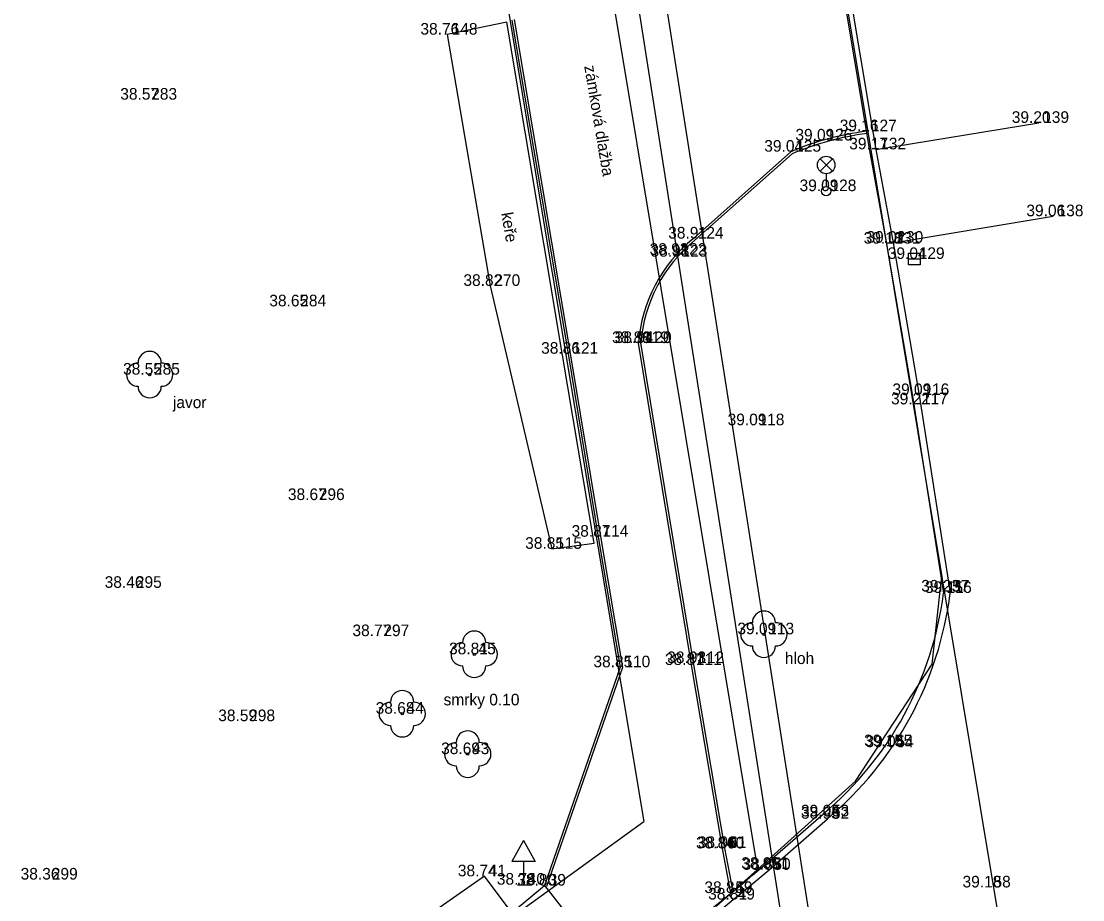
# Model space of a CAD drawing. Extents: x -609709 to -609357, y -1051535 to -1051131.
# Drawn here: x -609522.37 to -609499.5, y -1051316.16 to -1051297.25 of the extents above; entities that cross this region are included whole.
import ezdxf

# ---------------------------------------------------------------- set-up
doc = ezdxf.new("R2010")
doc.units = 0
for name, color, linetype in [('Vrstva 1', 7, 'Continuous'), ('Vrstva 10', 7, 'Continuous'), ('Vrstva 19', 7, 'Continuous'), ('Vrstva 2', 7, 'Continuous'), ('Vrstva 3', 7, 'Continuous'), ('Vrstva 4', 7, 'Continuous'), ('Vrstva 5', 7, 'Continuous'), ('Vrstva 7', 7, 'Continuous')]:
    doc.layers.add(name, color=color, linetype=linetype)

msp = doc.modelspace()

# ---------------------------------------------------------------- linework, layer by layer
at = {"layer": 'Vrstva 1'}
for p, q in [((-609513.19, -1051297.54), (-609513.19, -1051297.54)), ((-609519.66, -1051298.94), (-609519.66, -1051298.94)), ((-609500.45, -1051299.44), (-609500.45, -1051299.44)), ((-609504.16, -1051299.62), (-609504.16, -1051299.62)), ((-609505.12, -1051299.82), (-609505.12, -1051299.82)), ((-609505.79, -1051300.06), (-609505.79, -1051300.06)), ((-609503.96, -1051300.01), (-609503.96, -1051300.01)), ((-609505.03, -1051300.91), (-609505.03, -1051300.91)), ((-609500.14, -1051301.45), (-609500.14, -1051301.45)), ((-609507.89, -1051301.93), (-609507.89, -1051301.93)), ((-609503.65, -1051302.04), (-609503.65, -1051302.04)), ((-609503.59, -1051302.02), (-609503.59, -1051302.02)), ((-609508.26, -1051302.28), (-609508.26, -1051302.28)), ((-609508.24, -1051302.32), (-609508.24, -1051302.32)), ((-609503.13, -1051302.37), (-609503.13, -1051302.37)), ((-609512.27, -1051302.95), (-609512.27, -1051302.95)), ((-609516.45, -1051303.39), (-609516.45, -1051303.39)), ((-609509.07, -1051304.18), (-609509.07, -1051304.18)), ((-609509.01, -1051304.18), (-609509.01, -1051304.18)), ((-609510.59, -1051304.41), (-609510.59, -1051304.41)), ((-609519.6, -1051304.86), (-609519.6, -1051304.86)), ((-609503.03, -1051305.3), (-609503.03, -1051305.3)), ((-609503.06, -1051305.5), (-609503.06, -1051305.5)), ((-609506.58, -1051305.95), (-609506.58, -1051305.95)), ((-609516.05, -1051307.56), (-609516.05, -1051307.56)), ((-609509.94, -1051308.35), (-609509.94, -1051308.35)), ((-609510.94, -1051308.61), (-609510.94, -1051308.61)), ((-609519.99, -1051309.45), (-609519.99, -1051309.45)), ((-609502.41, -1051309.53), (-609502.41, -1051309.53)), ((-609502.36, -1051309.56), (-609502.36, -1051309.56)), ((-609514.66, -1051310.49), (-609514.66, -1051310.49)), ((-609506.37, -1051310.45), (-609506.37, -1051310.45)), ((-609512.61, -1051310.88), (-609512.61, -1051310.88)), ((-609509.47, -1051311.16), (-609509.47, -1051311.16)), ((-609507.93, -1051311.11), (-609507.93, -1051311.11)), ((-609507.88, -1051311.07), (-609507.88, -1051311.07)), ((-609517.55, -1051312.32), (-609517.55, -1051312.32)), ((-609514.16, -1051312.16), (-609514.16, -1051312.16)), ((-609512.75, -1051313.03), (-609512.75, -1051313.03)), ((-609503.64, -1051312.86), (-609503.64, -1051312.86)), ((-609503.61, -1051312.88), (-609503.61, -1051312.88)), ((-609505, -1051314.37), (-609505, -1051314.37)), ((-609505, -1051314.42), (-609505, -1051314.42)), ((-609507.26, -1051315.06), (-609507.26, -1051315.06)), ((-609507.21, -1051315.05), (-609507.21, -1051315.05)), ((-609506.28, -1051315.5), (-609506.28, -1051315.5)), ((-609506.26, -1051315.52), (-609506.26, -1051315.52)), ((-609521.8, -1051315.73), (-609521.8, -1051315.73)), ((-609512.39, -1051315.66), (-609512.39, -1051315.66)), ((-609511.55, -1051315.84), (-609511.55, -1051315.84)), ((-609511.1, -1051315.86), (-609511.1, -1051315.86)), ((-609501.52, -1051315.9), (-609501.52, -1051315.9)), ((-609507.08, -1051316.02), (-609507.08, -1051316.02)), ((-609507.03, -1051316.16), (-609507.03, -1051316.16))]:
    msp.add_line(p, q, dxfattribs=at)
at = {"layer": 'Vrstva 10'}
for p, q in [((-609517.43, -1051249.92), (-609506.51, -1051315.51)), ((-609519.54, -1051251.09), (-609508.96, -1051314.48)), ((-609506.48, -1051285.5), (-609502.54, -1051309.21)), ((-609502.58, -1051309.58), (-609502.54, -1051309.21)), ((-609502.54, -1051309.21), (-609500.39, -1051322.14)), ((-609502.75, -1051311.09), (-609502.58, -1051309.58)), ((-609504.4, -1051313.61), (-609502.75, -1051311.09)), ((-609506.51, -1051315.51), (-609504.4, -1051313.61)), ((-609521.35, -1051323.44), (-609508.96, -1051314.48)), ((-609507.4, -1051316.31), (-609506.51, -1051315.51))]:
    msp.add_line(p, q, dxfattribs=at)
at = {"layer": 'Vrstva 19'}
for points in [[(-609513.91, -1051261.8), (-609509.35, -1051290.83), (-609510.76, -1051291.051), (-609510.504, -1051292.681), (-609509.17, -1051292.471), (-609503.272, -1051330.02)], [(-609514.503, -1051261.893), (-609510.036, -1051290.33), (-609511.446, -1051290.552), (-609511.003, -1051293.366), (-609509.669, -1051293.157), (-609503.864, -1051330.113)]]:
    msp.add_lwpolyline(points, dxfattribs=at)
at = {"layer": 'Vrstva 4'}
for p, q in [((-609507.858, -1051301.968), (-609505.763, -1051300.103)), ((-609506.351, -1051315.414), (-609505.091, -1051314.314))]:
    msp.add_line(p, q, dxfattribs=at)
for points in [[(-609510.637, -1051263.229), (-609509.507, -1051268.598), (-609508.568, -1051273.236), (-609507.958, -1051276.664), (-609506.798, -1051283.503), (-609506.248, -1051286.853), (-609505.068, -1051294.072), (-609504.758, -1051296.082), (-609504.098, -1051300.034), (-609503.728, -1051302.044), (-609503.168, -1051305.323), (-609502.501, -1051309.562)], [(-609510.5, -1051263.2), (-609509.37, -1051268.57), (-609508.43, -1051273.21), (-609507.82, -1051276.64), (-609506.66, -1051283.48), (-609506.11, -1051286.83), (-609504.93, -1051294.05), (-609504.62, -1051296.06), (-609503.96, -1051300.01), (-609503.59, -1051302.02), (-609503.03, -1051305.3), (-609502.36, -1051309.56)], [(-609511.8, -1051297.23), (-609510.59, -1051304.41), (-609509.94, -1051308.35), (-609509.47, -1051311.16), (-609511.1, -1051315.86)], [(-609511.752, -1051297.215), (-609510.541, -1051304.402), (-609509.891, -1051308.342), (-609509.419, -1051311.164), (-609511.053, -1051315.876)], [(-609503.96, -1051300.01), (-609500.45, -1051299.44)], [(-609507.89, -1051301.93), (-609505.79, -1051300.06)], [(-609503.59, -1051302.02), (-609500.14, -1051301.45)], [(-609507.08, -1051316.02), (-609507.26, -1051315.06), (-609507.93, -1051311.11), (-609509.07, -1051304.18)], [(-609507.036, -1051315.984), (-609507.211, -1051315.051), (-609507.881, -1051311.102), (-609509.02, -1051304.178)], [(-609506.26, -1051315.52), (-609505, -1051314.42)], [(-609506.26, -1051315.52), (-609506.351, -1051315.414)], [(-609521.45, -1051323.51), (-609519.34, -1051322.04), (-609515.08, -1051318.91), (-609511.77, -1051316.42), (-609511.1, -1051315.86), (-609509.43, -1051317.99)], [(-609507.03, -1051316.16), (-609507.118, -1051316.051)]]:
    msp.add_lwpolyline(points, dxfattribs=at)
for centre, radius, start, end in [((-609503.398, -1051305.684), 6.111, 97.1666, 113.046), ((-609503.398, -1051305.684), 6.061, 97.1666, 112.9686), ((-609505.893, -1051304.412), 3.186, 128.8237, 175.8273), ((-609505.893, -1051304.412), 3.136, 128.8009, 175.7195), ((-609509.869, -1051308.628), 7.426, 310.041, 352.7752), ((-609509.869, -1051308.628), 7.566, 310.0511, 352.9264), ((-609539.416, -1051276.412), 51.131, 307.2963, 310.2906), ((-609539.416, -1051276.412), 51.271, 307.2948, 310.2918)]:
    msp.add_arc(centre, radius, start, end, dxfattribs=at)
at = {"layer": 'Vrstva 5'}
for p, q in [((-609505.162, -1051300.48), (-609504.897, -1051300.215)), ((-609505.162, -1051300.215), (-609504.897, -1051300.48)), ((-609505.03, -1051300.535), (-609505.03, -1051300.81)), ((-609503.255, -1051302.37), (-609503.005, -1051302.37)), ((-609511.55, -1051314.89), (-609511.8, -1051315.34)), ((-609511.55, -1051314.89), (-609511.3, -1051315.34)), ((-609511.3, -1051315.34), (-609511.8, -1051315.34)), ((-609511.55, -1051315.34), (-609511.55, -1051315.84)), ((-609511.675, -1051315.84), (-609511.425, -1051315.84))]:
    msp.add_line(p, q, dxfattribs=at)
msp.add_lwpolyline([(-609503.255, -1051302.245), (-609503.005, -1051302.245), (-609503.005, -1051302.495), (-609503.255, -1051302.495)], close=True, dxfattribs=at)
for centre, radius in [((-609505.03, -1051300.347), 0.188), ((-609505.03, -1051300.91), 0.1)]:
    msp.add_circle(centre, radius, dxfattribs=at)
at = {"layer": 'Vrstva 7'}
for points in [[(-609510.94, -1051308.61), (-609510.03, -1051308.49), (-609510.71, -1051304.44), (-609511.91, -1051297.27), (-609513.19, -1051297.54), (-609512.27, -1051302.95), (-609510.94, -1051308.61)], [(-609512.39, -1051315.66), (-609516.95, -1051318.84), (-609520.09, -1051321.08), (-609519.43, -1051321.98), (-609515.15, -1051318.85), (-609511.88, -1051316.34), (-609512.39, -1051315.66)]]:
    msp.add_lwpolyline(points, dxfattribs=at)
for centre in [(-609519.6, -1051304.86), (-609506.37, -1051310.45), (-609512.61, -1051310.88), (-609514.16, -1051312.16), (-609512.75, -1051313.03)]:
    msp.add_circle(centre, 0.025, dxfattribs=at)
for centre, start, end in [((-609519.6, -1051304.61), 0, 180), ((-609519.85, -1051304.86), 90, 270), ((-609519.35, -1051304.86), 270, 90), ((-609519.6, -1051305.11), 180, 0), ((-609506.37, -1051310.2), 0, 180), ((-609506.62, -1051310.45), 90, 270), ((-609506.12, -1051310.45), 270, 90), ((-609512.61, -1051310.63), 0, 180), ((-609512.86, -1051310.88), 90, 270), ((-609512.36, -1051310.88), 270, 90), ((-609506.37, -1051310.7), 180, 0), ((-609512.61, -1051311.13), 180, 0), ((-609514.16, -1051311.91), 0, 180), ((-609514.41, -1051312.16), 90, 270), ((-609513.91, -1051312.16), 270, 90), ((-609514.16, -1051312.41), 180, 0), ((-609512.75, -1051312.78), 0, 180), ((-609513, -1051313.03), 90, 270), ((-609512.5, -1051313.03), 270, 90), ((-609512.75, -1051313.28), 180, 0)]:
    msp.add_arc(centre, 0.25, start, end, dxfattribs=at)

# ---------------------------------------------------------------- texts
at = {"layer": 'Vrstva 2'}
for s, p in [(' 148', (-609513.19, -1051297.54)), (' 283', (-609519.66, -1051298.94)), (' 139', (-609500.45, -1051299.44)), (' 127', (-609504.16, -1051299.62)), (' 126', (-609505.12, -1051299.82)), (' 132', (-609503.96, -1051300.01)), (' 125', (-609505.79, -1051300.06)), (' 128', (-609505.03, -1051300.91)), (' 138', (-609500.14, -1051301.45)), (' 124', (-609507.89, -1051301.93)), (' 131', (-609503.65, -1051302.04)), (' 130', (-609503.59, -1051302.02)), (' 122', (-609508.26, -1051302.28)), (' 123', (-609508.24, -1051302.32)), (' 129', (-609503.13, -1051302.37)), (' 270', (-609512.27, -1051302.95)), (' 284', (-609516.45, -1051303.39)), (' 119', (-609509.07, -1051304.18)), (' 120', (-609509.01, -1051304.18)), (' 121', (-609510.59, -1051304.41)), (' 285', (-609519.6, -1051304.86)), (' 117', (-609503.06, -1051305.5)), (' 116', (-609503.03, -1051305.3)), (' 118', (-609506.58, -1051305.95)), (' 296', (-609516.05, -1051307.56)), (' 114', (-609509.94, -1051308.35)), (' 115', (-609510.94, -1051308.61)), (' 295', (-609519.99, -1051309.45)), (' 57', (-609502.41, -1051309.53)), (' 56', (-609502.36, -1051309.56)), (' 297', (-609514.66, -1051310.49)), (' 113', (-609506.37, -1051310.45)), (' 45', (-609512.61, -1051310.88)), (' 110', (-609509.47, -1051311.16)), (' 111', (-609507.93, -1051311.11)), (' 112', (-609507.88, -1051311.07)), (' 298', (-609517.55, -1051312.32)), (' 44', (-609514.16, -1051312.16)), (' 43', (-609512.75, -1051313.03)), (' 55', (-609503.64, -1051312.86)), (' 54', (-609503.61, -1051312.88)), (' 53', (-609505, -1051314.37)), (' 52', (-609505, -1051314.42)), (' 60', (-609507.26, -1051315.06)), (' 61', (-609507.21, -1051315.05)), (' 51', (-609506.28, -1051315.5)), (' 50', (-609506.26, -1051315.52)), (' 299', (-609521.8, -1051315.73)), (' 41', (-609512.39, -1051315.66)), (' 40', (-609511.55, -1051315.84)), (' 39', (-609511.1, -1051315.86)), (' 59', (-609507.08, -1051316.02)), (' 58', (-609501.52, -1051315.9)), (' 49', (-609507.03, -1051316.16))]:
    msp.add_text(s, height=0.25, dxfattribs=at).set_placement(p)
at = {"layer": 'Vrstva 3'}
for s, p in [('38.76', (-609513.769, -1051297.54)), ('38.57', (-609520.233, -1051298.94)), ('39.20', (-609501.033, -1051299.44)), ('39.16', (-609504.739, -1051299.62)), ('39.09', (-609505.693, -1051299.82)), ('39.17', (-609504.533, -1051300.01)), ('39.04', (-609506.363, -1051300.06)), ('39.09', (-609505.603, -1051300.91)), ('39.06', (-609500.719, -1051301.45)), ('38.91', (-609508.432, -1051301.93)), ('39.18', (-609504.223, -1051302.04)), ('39.02', (-609504.163, -1051302.02)), ('38.92', (-609508.833, -1051302.28)), ('38.98', (-609508.813, -1051302.32)), ('39.04', (-609503.703, -1051302.37)), ('38.82', (-609512.843, -1051302.95)), ('38.65', (-609517.023, -1051303.39)), ('38.88', (-609509.643, -1051304.18)), ('38.94', (-609509.583, -1051304.18)), ('38.86', (-609511.169, -1051304.41)), ('38.55', (-609520.173, -1051304.86)), ('39.22', (-609503.633, -1051305.5)), ('39.09', (-609503.603, -1051305.3)), ('39.09', (-609507.153, -1051305.95)), ('38.67', (-609516.623, -1051307.56)), ('38.87', (-609510.513, -1051308.35)), ('38.85', (-609511.513, -1051308.61)), ('38.46', (-609520.569, -1051309.45)), ('39.23', (-609502.983, -1051309.53)), ('39.11', (-609502.902, -1051309.56)), ('38.77', (-609515.233, -1051310.49)), ('39.09', (-609506.943, -1051310.45)), ('38.81', (-609513.152, -1051310.88)), ('38.85', (-609510.043, -1051311.16)), ('38.87', (-609508.503, -1051311.11)), ('38.93', (-609508.453, -1051311.07)), ('38.59', (-609518.123, -1051312.32)), ('38.68', (-609514.733, -1051312.16)), ('38.69', (-609513.323, -1051313.03)), ('39.15', (-609504.213, -1051312.86)), ('39.04', (-609504.183, -1051312.88)), ('38.95', (-609505.573, -1051314.42)), ('39.04', (-609505.573, -1051314.37)), ('38.84', (-609507.833, -1051315.06)), ('38.90', (-609507.793, -1051315.05)), ('38.96', (-609506.859, -1051315.5)), ('38.87', (-609506.833, -1051315.52)), ('38.36', (-609522.379, -1051315.73)), ('38.74', (-609512.963, -1051315.66)), ('38.78', (-609512.123, -1051315.84)), ('38.80', (-609511.683, -1051315.86)), ('38.84', (-609507.653, -1051316.02)), ('39.18', (-609502.093, -1051315.9)), ('38.81', (-609507.572, -1051316.16))]:
    msp.add_text(s, height=0.25, dxfattribs=at).set_placement(p)
at = {"layer": 'Vrstva 4'}
msp.add_text('zámková dlažba', height=0.25, rotation=279.5658, dxfattribs=at).set_placement((-609510.242, -1051298.221))
at = {"layer": 'Vrstva 7'}
msp.add_text('keře', height=0.25, rotation=279.6511, dxfattribs=at).set_placement((-609512.029, -1051301.386))
for s, p in [('javor', (-609519.1, -1051305.58)), ('hloh', (-609505.92, -1051311.09)), ('smrky 0.10', (-609513.27, -1051311.98))]:
    msp.add_text(s, height=0.25, dxfattribs=at).set_placement(p)

doc.saveas('drawing.dxf')
